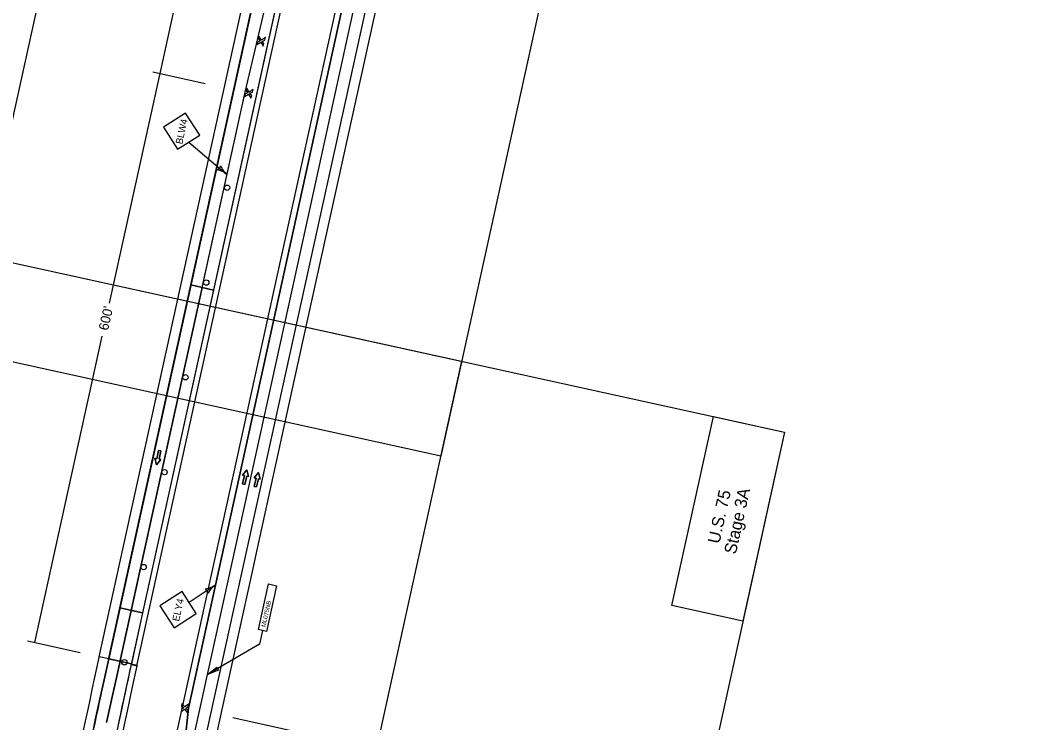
# Model space of a CAD drawing. Extents: x 14104283 to 14120882, y 8635219 to 8671666.
# Drawn here: x 14108027 to 14109077, y 8640895 to 8641619 of the extents above; entities that cross this region are included whole.
import ezdxf

# ---------------------------------------------------------------- set-up
doc = ezdxf.new("R2010")
doc.units = 0
for name, color, linetype in [('Cell', 7, 'Continuous'), ('dsnNonPlotable', 7, 'Continuous'), ('dsnPaintExistingEdgeLineRightWhite', 7, 'Continuous'), ('dsnPaintPlaceBrokenLineWhite', 7, 'Continuous'), ('dsnPaintPlaceEdgeLineLeftYellow', 7, 'Continuous'), ('dsnPaintPlaceEdgeLineRightWhite', 7, 'Continuous'), ('dsnPaintRemoveDoubleCenterLineYellow', 7, 'Continuous'), ('dsnShadingPaved', 7, 'Continuous'), ('dsnStdLabel', 7, 'Continuous'), ('dsnStgShadingPrevPav', 7, 'Continuous'), ('dsnTapePlaceChannelizingLaneYellow', 7, 'Continuous'), ('dsnTextOverlapOdd', 7, 'Continuous'), ('Text', 7, 'Continuous')]:
    doc.layers.add(name, color=color, linetype=linetype)

msp = doc.modelspace()

# ---------------------------------------------------------------- linework, layer by layer
at = {"layer": 'Cell'}
for p, q in [((14108270.8, 8641596.3), (14108270.2, 8641593.7)), ((14108270.2, 8641593.7), (14108274.3, 8641596.2)), ((14108273.4, 8641597.5), (14108270.8, 8641596.3)), ((14108272.3, 8641602.4), (14108271.7, 8641599.7)), ((14108271.7, 8641599.7), (14108273.4, 8641597.5)), ((14108274.8, 8641598.3), (14108272.3, 8641602.4)), ((14108274.3, 8641596.2), (14108276.7, 8641592.1)), ((14108278.9, 8641600.8), (14108274.8, 8641598.3)), ((14108275.6, 8641597), (14108278.2, 8641598.2)), ((14108277.4, 8641594.8), (14108275.6, 8641597)), ((14108276.7, 8641592.1), (14108277.4, 8641594.8)), ((14108278.2, 8641598.2), (14108278.9, 8641600.8)), ((14108258.2, 8641542.8), (14108257.5, 8641540.1)), ((14108257.5, 8641540.1), (14108261.6, 8641542.6)), ((14108260.8, 8641544), (14108258.2, 8641542.8)), ((14108259.7, 8641548.9), (14108259, 8641546.2)), ((14108259, 8641546.2), (14108260.8, 8641544)), ((14108262.2, 8641544.8), (14108259.7, 8641548.9)), ((14108261.6, 8641542.6), (14108264.1, 8641538.6)), ((14108266.2, 8641547.3), (14108262.2, 8641544.8)), ((14108263, 8641543.5), (14108265.6, 8641544.6)), ((14108264.8, 8641541.2), (14108263, 8641543.5)), ((14108264.1, 8641538.6), (14108264.8, 8641541.2)), ((14108265.6, 8641544.6), (14108266.2, 8641547.3)), ((14108194.8, 8640910.5), (14108192.4, 8640909)), ((14108193, 8640915.2), (14108192.7, 8640912.5)), ((14108192.7, 8640912.5), (14108194.8, 8640910.5)), ((14108196, 8640911.5), (14108193, 8640915.2)), ((14108199.7, 8640914.5), (14108196, 8640911.5)), ((14108197.1, 8640910.3), (14108199.5, 8640911.8)), ((14108199.1, 8640908.3), (14108197.1, 8640910.3)), ((14108199.5, 8640911.8), (14108199.7, 8640914.5)), ((14108192.1, 8640906.2), (14108195.8, 8640909.3)), ((14108192.4, 8640909), (14108192.1, 8640906.2)), ((14108195.8, 8640909.3), (14108198.9, 8640905.6)), ((14108198.9, 8640905.6), (14108199.1, 8640908.3))]:
    msp.add_line(p, q, dxfattribs=at)
for points in [[(14108168.9, 8641175.7), (14108171.3, 8641175.2), (14108169.5, 8641166.6), (14108171.3, 8641166.2), (14108166.9, 8641160.8), (14108165.2, 8641167.6), (14108167, 8641167.2)], [(14108257.9, 8641140.7), (14108255.4, 8641141.3), (14108257.3, 8641149.8), (14108255.5, 8641150.2), (14108259.8, 8641155.6), (14108261.6, 8641148.9), (14108259.7, 8641149.3)], [(14108269.9, 8641138.1), (14108267.5, 8641138.6), (14108269.3, 8641147.2), (14108267.5, 8641147.6), (14108271.9, 8641153), (14108273.6, 8641146.2), (14108271.8, 8641146.6)]]:
    msp.add_lwpolyline(points, close=True, dxfattribs=at)
for points in [[(14108167, 8641167.2), (14108165.2, 8641167.6), (14108166.9, 8641160.8), (14108171.3, 8641166.2), (14108169.5, 8641166.6), (14108171.3, 8641175.2), (14108168.9, 8641175.7), (14108167, 8641167.2)], [(14108259.7, 8641149.3), (14108261.6, 8641148.9), (14108259.8, 8641155.6), (14108255.5, 8641150.2), (14108257.3, 8641149.8), (14108255.4, 8641141.3), (14108257.9, 8641140.7), (14108259.7, 8641149.3)], [(14108271.8, 8641146.6), (14108273.6, 8641146.2), (14108271.9, 8641153), (14108267.5, 8641147.6), (14108269.3, 8641147.2), (14108267.5, 8641138.6), (14108269.9, 8641138.1), (14108271.8, 8641146.6)]]:
    msp.add_lwpolyline(points, dxfattribs=at)
for centre in [(14108239.5, 8641446.3), (14108218, 8641348.6), (14108196.6, 8641251), (14108175.1, 8641153.3), (14108153.6, 8641055.6), (14108133.8, 8640957.6)]:
    msp.add_circle(centre, 2.75, dxfattribs=at)
at = {"layer": 'dsnNonPlotable'}
for points in [[(14107966.2, 8641278.2), (14108302.6, 8642809.2), (14108795.9, 8642700.9), (14108459.5, 8641169.9)], [(14107490.5, 8639880.3), (14107826.8, 8641411.3), (14108813.3, 8641194.5), (14108476.9, 8639663.5)], [(14107651.3, 8639844.9), (14107987.7, 8641375.9), (14108480.9, 8641267.5), (14108144.5, 8639736.6)]]:
    msp.add_lwpolyline(points, close=True, dxfattribs=at)
at = {"layer": 'dsnPaintExistingEdgeLineRightWhite'}
msp.add_line((14108201.6, 8640807.6), (14108724, 8643185.7), dxfattribs=at)
at = {"layer": 'dsnPaintPlaceBrokenLineWhite'}
for p, q in [((14108129.1, 8640957.7), (14108258, 8641544.6)), ((14108189.8, 8640810.1), (14108306.4, 8641340.7)), ((14108115.4, 8640895.4), (14108129.3, 8640958.6))]:
    msp.add_line(p, q, dxfattribs=at)
msp.add_lwpolyline([(14108306.4, 8641340.7), (14108389, 8641717), (14108712.3, 8643188.3), (14108894.6, 8644035.3), (14109077, 8644882.2)], dxfattribs=at)
at = {"layer": 'dsnPaintPlaceEdgeLineLeftYellow'}
msp.add_line((14108199.6, 8640910.3), (14108700.5, 8643190.8), dxfattribs=at)
at = {"layer": 'dsnPaintPlaceEdgeLineRightWhite'}
for p, q in [((14108202.1, 8641346.1), (14108117.6, 8640961.2)), ((14108117.6, 8640961.2), (14108103.7, 8640898))]:
    msp.add_line(p, q, dxfattribs=at)
msp.add_lwpolyline([(14108976.3, 8644903.9), (14108611.6, 8643210.2), (14108202.1, 8641346.1)], dxfattribs=at)
msp.add_arc((14117394.1, 8638857.1), 9512, 167.61021, 168.00312, dxfattribs=at)
at = {"layer": 'dsnPaintRemoveDoubleCenterLineYellow'}
msp.add_line((14108099.1, 8640397), (14108306.4, 8641340.7), dxfattribs=at)
msp.add_lwpolyline([(14108306.4, 8641340.7), (14108389, 8641717), (14108712.3, 8643188.3), (14108894.6, 8644035.3), (14109077, 8644882.2)], dxfattribs=at)
at = {"layer": 'dsnShadingPaved'}
for p, q in [((14108700.5, 8643190.9), (14108199.6, 8640910.3)), ((14108201.6, 8640807.6), (14108724, 8643185.7)), ((14108258, 8641544.6), (14108434.9, 8642294.1)), ((14108213.8, 8641343.5), (14108258, 8641544.6)), ((14108117.4, 8640960.3), (14108202.1, 8641346.1)), ((14108213.8, 8641343.5), (14108129.1, 8640957.7)), ((14108202.1, 8641346.1), (14108213.8, 8641343.5)), ((14108103.7, 8640898), (14108117.6, 8640961.2)), ((14108129.3, 8640958.6), (14108115.4, 8640895.4)), ((14108199.6, 8640910.3), (14108189.8, 8640810.1))]:
    msp.add_line(p, q, dxfattribs=at)
msp.add_lwpolyline([(14108976.3, 8644903.9), (14108611.6, 8643210.2), (14108202.1, 8641346.1)], dxfattribs=at)
msp.add_arc((14117394.1, 8638857.1), 9512, 167.61021, 171.32599, dxfattribs=at)
at = {"layer": 'dsnStdLabel'}
for p, q in [((14108335.3, 8642316), (14108170.1, 8641563.9)), ((14108170.1, 8641563.9), (14108118.1, 8641327.4)), ((14108162.9, 8641565.5), (14108217, 8641553.6)), ((14108200, 8641493.2), (14108239.4, 8641459.8)), ((14108110.7, 8641293.4), (14108041.4, 8640977.9)), ((14108227.1, 8641036.8), (14108200.4, 8641019)), ((14108034.1, 8640979.5), (14108088.3, 8640967.6)), ((14108305.5, 8640887), (14108245.5, 8640900.2))]:
    msp.add_line(p, q, dxfattribs=at)
for points in [[(14108188.6, 8641485.9), (14108211.4, 8641500.5), (14108196.8, 8641523.2), (14108174.1, 8641508.6)], [(14108185, 8640993.1), (14108207.7, 8641007.7), (14108193.2, 8641030.4), (14108170.4, 8641015.8)]]:
    msp.add_lwpolyline(points, close=True, dxfattribs=at)
for centre, radius, start, end in [((14108224.7, 8641472.2), 8.86, 301.9754, 337.4439), ((14108254.2, 8641477.3), 22.9, 201.6384, 229.7097), ((14108224.6, 8641442.3), 22.9, 49.7096, 77.7809), ((14108214.8, 8641056.1), 22.9, 275.2387, 303.31), ((14108240, 8641017.7), 22.9, 123.3098, 151.3811), ((14108211.3, 8641026.3), 8.86, 15.5757, 51.0441)]:
    msp.add_arc(centre, radius, start, end, dxfattribs=at)
at = {"layer": 'dsnStgShadingPrevPav'}
for p, q in [((14108107.8, 8640963.3), (14108601.8, 8643212.3)), ((14108611.6, 8643210.2), (14108117.6, 8640961.2)), ((14108225.5, 8641340.9), (14108202.1, 8641346.1)), ((14108107.8, 8640963.3), (14108107.6, 8640962.4)), ((14108117.6, 8640961.2), (14108107.8, 8640963.3)), ((14108117.6, 8640961.2), (14108107.8, 8640963.3)), ((14108117.4, 8640960.3), (14108117.6, 8640961.2)), ((14108140.8, 8640955.1), (14108141, 8640956)), ((14108140.8, 8640955.1), (14108146.7, 8640953.8)), ((14108141, 8640956), (14108146.9, 8640954.7)), ((14108146.9, 8640954.7), (14108146.7, 8640953.8))]:
    msp.add_line(p, q, dxfattribs=at)
for points in [[(14108202.1, 8641346.1), (14108611.6, 8643210.2), (14108976.3, 8644903.9)], [(14108999.8, 8644898.8), (14108817.4, 8644052), (14108635.1, 8643205.1), (14108387.9, 8642080.1), (14108140.8, 8640955.1)], [(14108146.7, 8640953.8), (14108640.9, 8643203.9), (14109005.6, 8644897.6)], [(14108999.8, 8644898.8), (14108635.1, 8643205.1), (14108225.5, 8641340.9)], [(14108117.4, 8640960.3), (14108117.6, 8640961.2), (14108141, 8640956), (14108140.8, 8640955.1)]]:
    msp.add_lwpolyline(points, dxfattribs=at)
for points in [[(14108081.5, 8640400.9), (14108123.3, 8640591.3), (14108126.6, 8640606), (14108216.7, 8641016.2), (14108268.2, 8641250.6), (14108383, 8641773.2), (14108422, 8641764.6), (14108309.4, 8641251.8), (14108270.2, 8641073.5), (14108265.9, 8641054), (14108255.7, 8641007.6), (14108202.1, 8640763.4), (14108120.6, 8640392.3)], [(14108129.1, 8641013.6), (14108202.1, 8641346.1), (14108225.5, 8641340.9), (14108152.5, 8641008.5)], [(14108141, 8640956), (14108117.6, 8640961.2), (14108129.1, 8641013.6), (14108152.5, 8641008.5)]]:
    msp.add_lwpolyline(points, close=True, dxfattribs=at)
for radius, end in [(9522, 168.68895), (9488, 172.22208), (9482, 172.22208), (9512, 168.32826), (9512, 168.32826), (9488, 168.32826)]:
    msp.add_arc((14117407.8, 8638919.4), radius, 167.61021, end, dxfattribs=at)
at = {"layer": 'dsnTapePlaceChannelizingLaneYellow'}
for p, q in [((14108258, 8641544.6), (14108434.9, 8642294.1)), ((14108189.8, 8640810.1), (14108199.6, 8640910.3))]:
    msp.add_line(p, q, dxfattribs=at)
at = {"layer": 'dsnTextOverlapOdd'}
for points in [[(14108813.3, 8641194.5), (14108770.5, 8640999.9), (14108697.3, 8641016), (14108740.1, 8641210.6)], [(14108697.3, 8641016), (14108740.1, 8641210.6), (14108813.3, 8641194.5), (14108770.5, 8640999.9)]]:
    msp.add_lwpolyline(points, close=True, dxfattribs=at)
at = {"layer": 'Text'}
for points in [[(14108271.8, 8640991.2), (14108282.1, 8641038.2), (14108290.3, 8641036.4), (14108280, 8640989.4)], [(14108271.8, 8640991.2), (14108282.1, 8641038.2), (14108290.3, 8641036.4), (14108280, 8640989.4)], [(14108219.5, 8640945.1), (14108228.8, 8640952.6), (14108230.6, 8640949.5)]]:
    msp.add_lwpolyline(points, close=True, dxfattribs=at)
msp.add_lwpolyline([(14108275.9, 8640990.3), (14108272.8, 8640976.3), (14108219.5, 8640945.1)], dxfattribs=at)

# ---------------------------------------------------------------- texts
at = {"layer": 'dsnStdLabel'}
for s, height, rotation, p in [('BLW4', 7.2, 77.6078, (14108193.3, 8641490.6)), ("600'", 10, 77.0531, (14108116.8, 8641298.6)), ('ELY4', 7.2, 77.6078, (14108190, 8640999.2))]:
    msp.add_text(s, height=height, rotation=rotation, dxfattribs=at).set_placement(p)
at = {"layer": 'dsnTextOverlapOdd'}
for s, p in [('U.S. 75', (14108746.3, 8641079)), ('Stage 3A', (14108763.2, 8641068.2))]:
    msp.add_text(s, height=12.5, rotation=77.6078, dxfattribs=at).set_placement(p)
at = {"layer": 'Text'}
msp.add_text('ML075NB', height=4.48, rotation=77.6078, dxfattribs=at).set_placement((14108279, 8640993.5))

doc.saveas('drawing.dxf')
